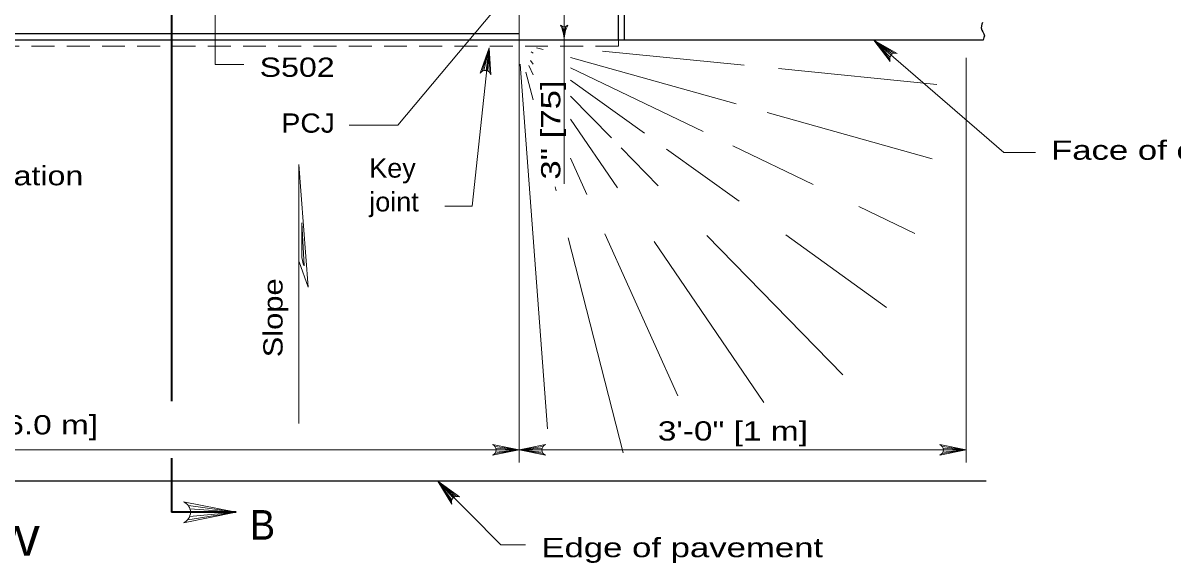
# Model space of a CAD drawing. Extents: x 758.3 to 792.3, y 849.7 to 893.7.
# Drawn here: x 771.26 to 780.59, y 882.81 to 887.19 of the extents above; entities that cross this region are included whole.
import ezdxf

# ---------------------------------------------------------------- set-up
doc = ezdxf.new("R2010")
doc.units = 0
doc.header["$LTSCALE"] = 0.062
doc.linetypes.add('MEDIUM_DASHED', pattern=[4.5, 3, -1.5])
doc.layers.add('1', color=7, linetype='Continuous', lineweight=13)

msp = doc.modelspace()

# ---------------------------------------------------------------- linework, layer by layer
at = {"layer": '1', "lineweight": 25}
for p, q in [((776.08867, 887.05092), (776.08867, 891.08192)), ((775.28242, 887.10125), (765.70775, 887.10125))]:
    msp.add_line(p, q, dxfattribs=at)
at = {"layer": '1', "linetype": 'MEDIUM_DASHED'}
for p, q in [((775.28242, 887.10125), (775.28242, 890.32608)), ((776.08867, 887.0005), (764.9015, 887.0005))]:
    msp.add_line(p, q, dxfattribs=at)
at = {"layer": '1'}
for p, q in [((772.81558, 886.85167), (772.81558, 889.77183)), ((775.64833, 887.35325), (775.64833, 885.88517)), ((776.08867, 887.0005), (776.08867, 887.05092)), ((778.3005, 886.9295), (778.1605, 887.05092)), ((778.29167, 886.91408), (778.1605, 887.05092)), ((778.289, 886.89975), (778.1605, 887.05092)), ((778.311, 886.9385), (778.1605, 887.05092)), ((778.32475, 886.94433), (778.1605, 887.05092)), ((774.98317, 886.79758), (775.03983, 886.98783)), ((774.99667, 886.80325), (775.03983, 886.98783)), ((775.01442, 886.80425), (775.03983, 886.98783)), ((775.02767, 886.80042), (775.03983, 886.98783)), ((775.04008, 886.792), (775.03983, 886.98783)), ((775.39575, 886.94467), (775.38075, 886.9555)), ((775.4775, 886.97333), (775.42408, 886.98833)), ((777.04317, 886.53325), (775.70033, 886.91067)), ((777.10867, 886.84667), (775.96033, 886.96133)), ((778.91067, 883.62567), (778.91067, 886.906)), ((772.81558, 886.85167), (773.04933, 886.85167)), ((775.29075, 886.85458), (775.51308, 883.89683)), ((775.36092, 886.84525), (775.39575, 886.768)), ((775.37642, 886.88475), (775.39575, 886.85642)), ((776.77667, 886.30825), (775.70033, 886.82617)), ((778.67158, 886.69075), (777.38633, 886.819)), ((775.33833, 886.7915), (775.39575, 886.56625)), ((776.29942, 886.29542), (775.70033, 886.72583)), ((775.70033, 886.59642), (776.032, 886.25667)), ((778.63383, 886.08617), (777.29458, 886.46258)), ((775.70033, 886.40992), (776.08075, 885.85225)), ((776.1105, 886.17625), (776.41083, 885.86858)), ((777.06783, 885.74325), (776.47933, 886.16617)), ((777.66892, 885.87875), (777.01808, 886.19192)), ((775.70033, 886.09333), (775.83358, 885.79817)), ((775.57558, 885.86092), (775.58367, 885.82917)), ((778.49458, 885.48142), (778.03883, 885.70075)), ((775.6815, 885.44542), (776.12592, 883.70225)), ((775.97808, 885.478), (776.57042, 884.16583)), ((776.37817, 885.41633), (777.26925, 884.11008)), ((776.8055, 885.46433), (777.90833, 884.33458)), ((778.265, 884.883), (777.4475, 885.47042)), ((775.28242, 883.72683), (771.9685, 883.72683)), ((775.08625, 883.69683), (775.28242, 883.72683)), ((775.0885, 883.75392), (775.28242, 883.72683)), ((775.09367, 883.70942), (775.28242, 883.72683)), ((775.09508, 883.7405), (775.28242, 883.72683)), ((775.09708, 883.72683), (775.28242, 883.72683)), ((775.47633, 883.75392), (775.28242, 883.72683)), ((775.46975, 883.7405), (775.28242, 883.72683)), ((777.60117, 883.72683), (775.28242, 883.72683)), ((775.46775, 883.72683), (775.28242, 883.72683)), ((775.47117, 883.70942), (775.28242, 883.72683)), ((775.47858, 883.69683), (775.28242, 883.72683)), ((778.91067, 883.72683), (777.60117, 883.72683)), ((778.7145, 883.69683), (778.91067, 883.72683)), ((778.71683, 883.75392), (778.91067, 883.72683)), ((778.72192, 883.70942), (778.91067, 883.72683)), ((778.72342, 883.7405), (778.91067, 883.72683)), ((778.72542, 883.72683), (778.91067, 883.72683)), ((774.74825, 883.33717), (774.62258, 883.47342)), ((774.73775, 883.32283), (774.62258, 883.47342)), ((774.73358, 883.30883), (774.62258, 883.47342)), ((774.75967, 883.345), (774.62258, 883.47342)), ((774.774, 883.34925), (774.62258, 883.47342)), ((772.599, 883.27492), (772.98675, 883.22067)), ((772.59442, 883.16067), (772.98675, 883.22067)), ((772.60925, 883.18583), (772.98675, 883.22067)), ((772.61208, 883.24808), (772.98675, 883.22067)), ((772.61608, 883.22067), (772.98675, 883.22067))]:
    msp.add_line(p, q, dxfattribs=at)
at = {"layer": '1', "lineweight": 35}
for p, q in [((772.46325, 884.85992), (772.46325, 884.43158)), ((772.46325, 884.43158), (772.46325, 884.12242)), ((772.46325, 883.66042), (772.46325, 883.22067)), ((772.98675, 883.22067), (772.46325, 883.22067))]:
    msp.add_line(p, q, dxfattribs=at)
msp.add_lwpolyline([(772.46325, 889.664), (772.46325, 886.0525), (772.46325, 884.85992)], dxfattribs=at)
at = {"layer": '1', "lineweight": 25}
for points in [[(776.13908, 887.05092), (776.13908, 887.55475), (779.047, 887.55475)], [(779.04267, 887.194), (779.0365, 887.17875), (779.03242, 887.15125), (779.03858, 887.12992), (779.04567, 887.11667), (779.05483, 887.1015), (779.05783, 887.08417), (779.05483, 887.072), (779.047, 887.05092)], [(779.047, 887.05092), (775.87267, 887.05092), (761.99533, 887.05092)], [(779.072, 883.47342), (773.49217, 883.47342), (767.821, 883.47342)]]:
    msp.add_lwpolyline(points, dxfattribs=at)
at = {"layer": '1'}
for points in [[(775.28242, 887.53625), (774.29892, 886.36058), (773.90367, 886.36058)], [(775.28242, 883.62567), (775.28242, 887.05092), (775.28242, 887.10125)], [(778.29417, 886.87825), (778.1605, 887.05092), (778.35033, 886.94292)], [(778.1605, 887.05092), (779.21642, 886.13817), (779.47242, 886.13817)], [(775.03983, 886.98783), (774.90167, 885.70408), (774.68133, 885.70408)], [(774.968, 886.78158), (775.03983, 886.98783), (775.05283, 886.76983)], [(773.49567, 883.94183), (773.49567, 886.0425), (773.57142, 885.04617), (773.49875, 885.25342)], [(773.53983, 885.22033), (773.52083, 885.56842), (773.52083, 885.28625), (773.53342, 885.22633)], [(771.9685, 883.72683), (765.70775, 883.72683), (764.05883, 883.72683)], [(775.06825, 883.684), (775.28242, 883.72683), (775.06825, 883.76967)], [(775.49658, 883.684), (775.28242, 883.72683), (775.49658, 883.76967)], [(778.6965, 883.684), (778.91067, 883.72683), (778.6965, 883.76967)], [(774.73633, 883.28692), (774.62258, 883.47342), (774.79925, 883.345)], [(774.62258, 883.47342), (775.13467, 882.95592), (775.3355, 882.95592)], [(772.55842, 883.135), (772.98675, 883.22067), (772.55842, 883.30633)]]:
    msp.add_lwpolyline(points, dxfattribs=at)
for centre, radius, start, end in [((778.33536, 886.89929), 0.04623, 71.15733, 206.98346), ((775.0081, 886.75854), 0.04623, 14.20106, 150.02719), ((775.05095, 883.72688), 0.04623, 292.08605, 67.91218), ((775.51388, 883.72688), 0.04623, 112.08782, 247.91395), ((778.67924, 883.72688), 0.04623, 292.08605, 67.91218), ((772.52383, 883.22073), 0.09245, 292.08605, 67.91218), ((774.77957, 883.30329), 0.04623, 64.78409, 200.61022)]:
    msp.add_arc(centre, radius, start, end, dxfattribs=at)
for centre, major_axis, ratio, start_param, end_param in [((775.64825, 887.21174), (0.04999, 0), 0.999895, 4.0628942, 5.3618844), ((775.38499, 887.04922), (0.26337, 0), 0.999895, 0.006388, 0.4847446), ((775.51403, 887.04827), (-0.00567, 0.26826), 0.500157, 4.7097543, 5.1482217), ((775.78237, 887.04827), (0.00567, 0.26826), 0.500157, 1.1353087, 1.5711709), ((775.91659, 887.04817), (-0.26836, 0), 0.999895, 5.8037911, 6.2726224)]:
    msp.add_ellipse(centre, major_axis=major_axis, ratio=ratio, start_param=start_param, end_param=end_param, dxfattribs=at)

# ---------------------------------------------------------------- texts
for s, height, width, p in [('S502', 0.156, 1.25, (773.17742, 886.7525)), ('PCJ', 0.156, 1.1, (773.35492, 886.29942)), ('Face of curb', 0.156, 1.35, (779.59892, 886.07983)), ('Key', 0.156, 1.05, (774.067, 885.935)), ('Reference station', 0.156, 1.25, (769.70283, 885.87283)), ('joint', 0.156, 1.05, (774.067, 885.661)), ("Variable 6' [1.8 m] to 20' [6.0 m]", 0.156, 1.3, (768.0555, 883.85242)), ('3\'-0" [1 m]', 0.156, 1.3, (776.40817, 883.8025)), ('B', 0.24, 0.95, (773.09933, 882.9985)), ('PLAN VIEW', 0.24, 1.25, (769.20967, 882.86992)), ('Edge of pavement', 0.156, 1.35, (775.46342, 882.8565))]:
    msp.add_text(s, height=height, dxfattribs=dict(at, width=width)).set_placement(p)
for s, width, p in [('3" [75]', 1.35, (775.61725, 885.91908)), ('Slope', 1.2, (773.36375, 884.47775))]:
    msp.add_text(s, height=0.156, rotation=90, dxfattribs=dict(at, width=width)).set_placement(p)

doc.saveas('drawing.dxf')
